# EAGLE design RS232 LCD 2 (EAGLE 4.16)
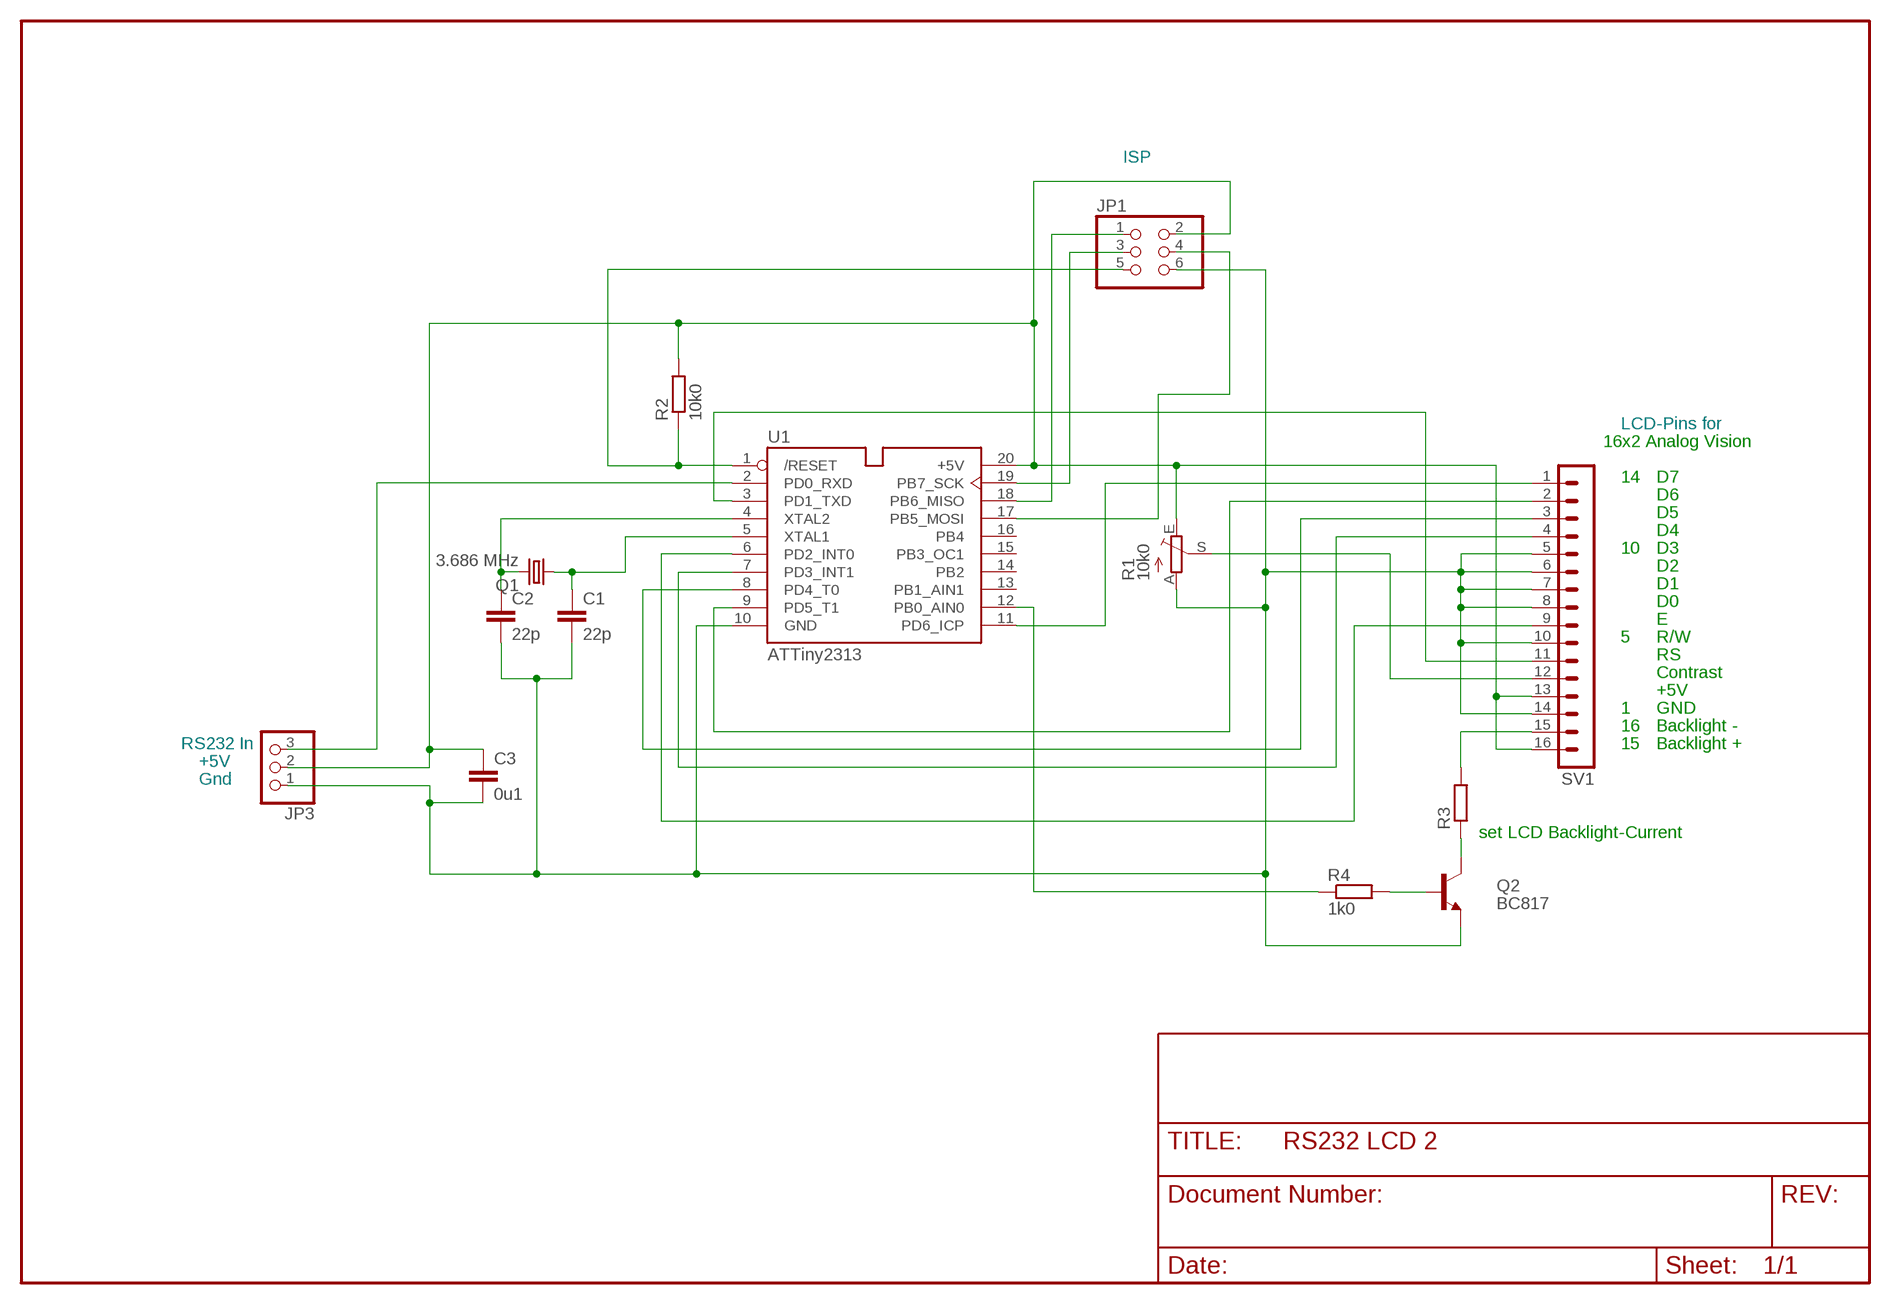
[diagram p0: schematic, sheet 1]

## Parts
C1  22p  C-EU050-025X075  [C050-025X075]
C2  22p  C-EU050-025X075  [C050-025X075]
C3  0u1  C-EU025-030X050  [C025-030X050]
JP1  PINHD-2X3  [2X03]
JP3  PINHD-1X3  [1X03]
Q1  3.686 MHz  CRYSTALHC18U-V  [HC18U-V]
Q2  BC817  BC817-16LT1SMD  [SOT23-BEC]
R1  10k0  TRIM_EU-PT10  [PT-10]
R2  10k0  R-EU_0207/10  [0207/10]
R3  R-EU_0207/10  [0207/10]
R4  1k0  R-EU_0207/10  [0207/10]
SV1  MA16-1  [MA16-1]
U1  ATTiny2313  AT90S2313_SO-20  [SO-20]

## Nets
+5V [Power]: C3.1 JP1.2 JP3.2 R1.E R2.2 SV1.13 SV1.16 U1.20(+5V)
BL- [Power]: R3.2 SV1.15
BL_BASE: Q2.B R4.2
BL_COLLECTOR: Q2.C R3.1
BL_CONTROL: R4.1 U1.12(PB0_AIN0)
CONTR: R1.S SV1.12
D4: SV1.4 U1.7(PD3_INT1)
D5: SV1.3 U1.8(PD4_T0)
D6: SV1.2 U1.9(PD5_T1)
D7: SV1.1 U1.11(PD6_ICP)
E: SV1.9 U1.6(PD2_INT0)
GND [Power]: C1.2 C2.2 C3.2 JP1.6 JP3.1 Q2.E R1.A SV1.5 SV1.6 SV1.7 SV1.8 SV1.10 SV1.14 U1.10(GND)
MISO: JP1.1 U1.18(PB6_MISO)
MOSI: JP1.4 U1.17(PB5_MOSI)
R/S: SV1.11 U1.3(PD1_TXD)
RST: JP1.5 R2.1 U1.1(/RESET)
RXD: JP3.3 U1.2(PD0_RXD)
SCK: JP1.3 U1.19(PB7_SCK)
XTAL1: C1.1 Q1.1 U1.5(XTAL1)
XTAL2: C2.1 Q1.2 U1.4(XTAL2)
Unconnected: U1.13(PB1_AIN1) U1.14(PB2) U1.15(PB3_OC1) U1.16(PB4)

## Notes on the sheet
- ISP
- LCD-Pins for
- 16x2 Analog Vision
- 14 | D7
- D6
- D5
- D4
- 10 | D3
- D2
- D1
- D0
- E
- 5 | R/W
- RS
- Contrast
- +5V
- 1 | GND
- 16 | Backlight -
- RS232 In | 15 | Backlight +
- +5V
- Gnd
- set LCD Backlight-Current

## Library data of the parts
C1-C3 = rcl:C-EU: CAPACITOR, European symbol
JP1 = pinhead:PINHD-2X3: PIN HEADER
JP3 = pinhead:PINHD-1X3: PIN HEADER
Q1 = crystal:CRYSTAL: CRYSTAL
Q2 = transistor-npn:BC817*: NPN Transistor
R1 = pot:TRIM_EU-: POTENTIOMETER
R2-R4 = rcl:R-EU_: RESISTOR, European symbol
SV1 = con-lstb:MA16-1
U1 = atmel_prototype_header:AT90S2313: 8-bit AVR Microcontroller with 2K bytes In-System Programmable Flash

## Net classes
0 default: width 0.254 mm
1 Power: width 0.635 mm

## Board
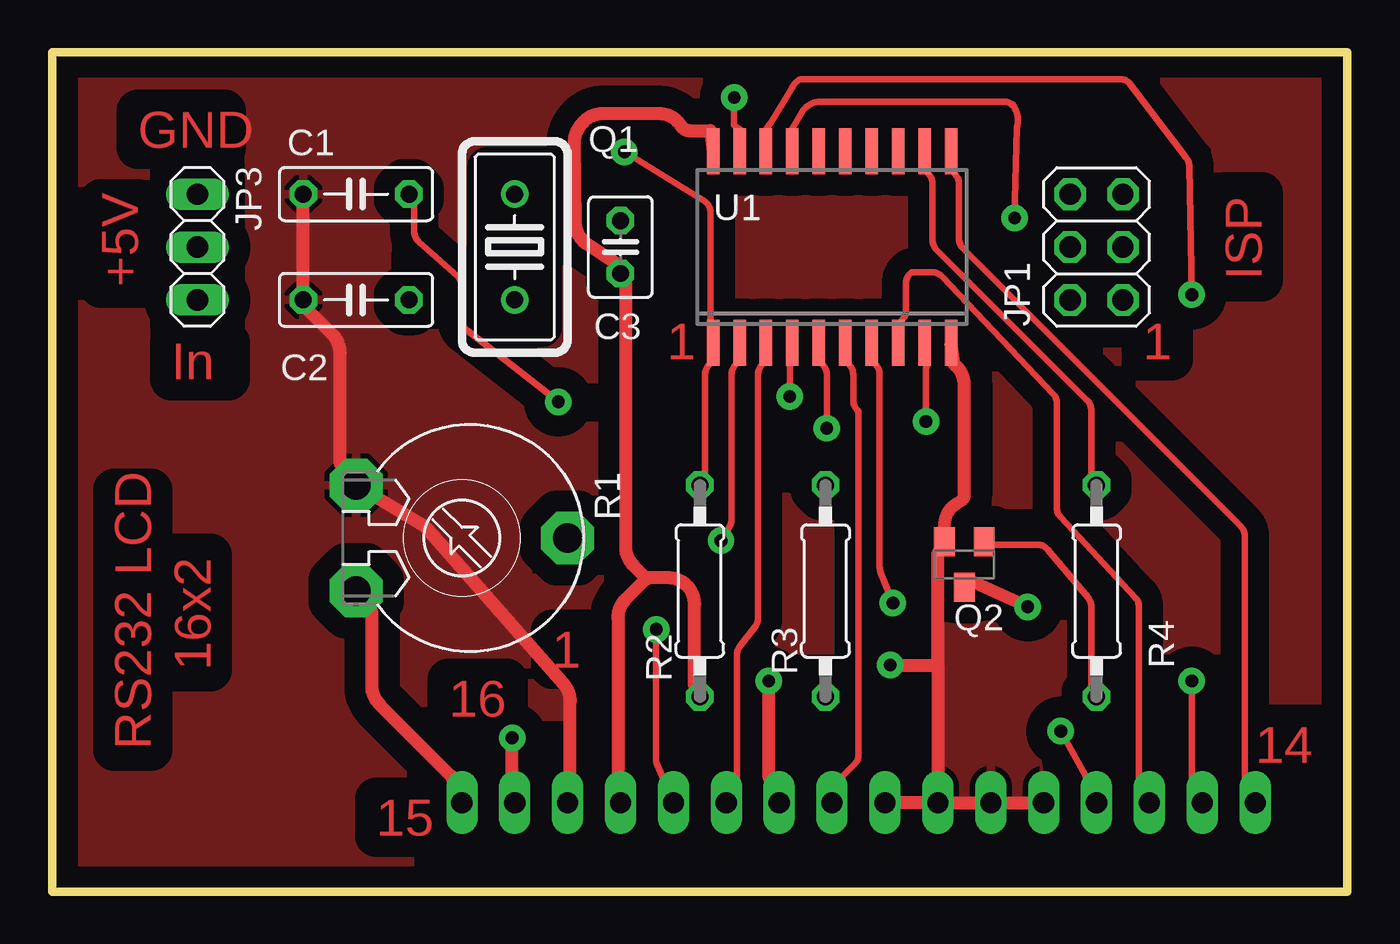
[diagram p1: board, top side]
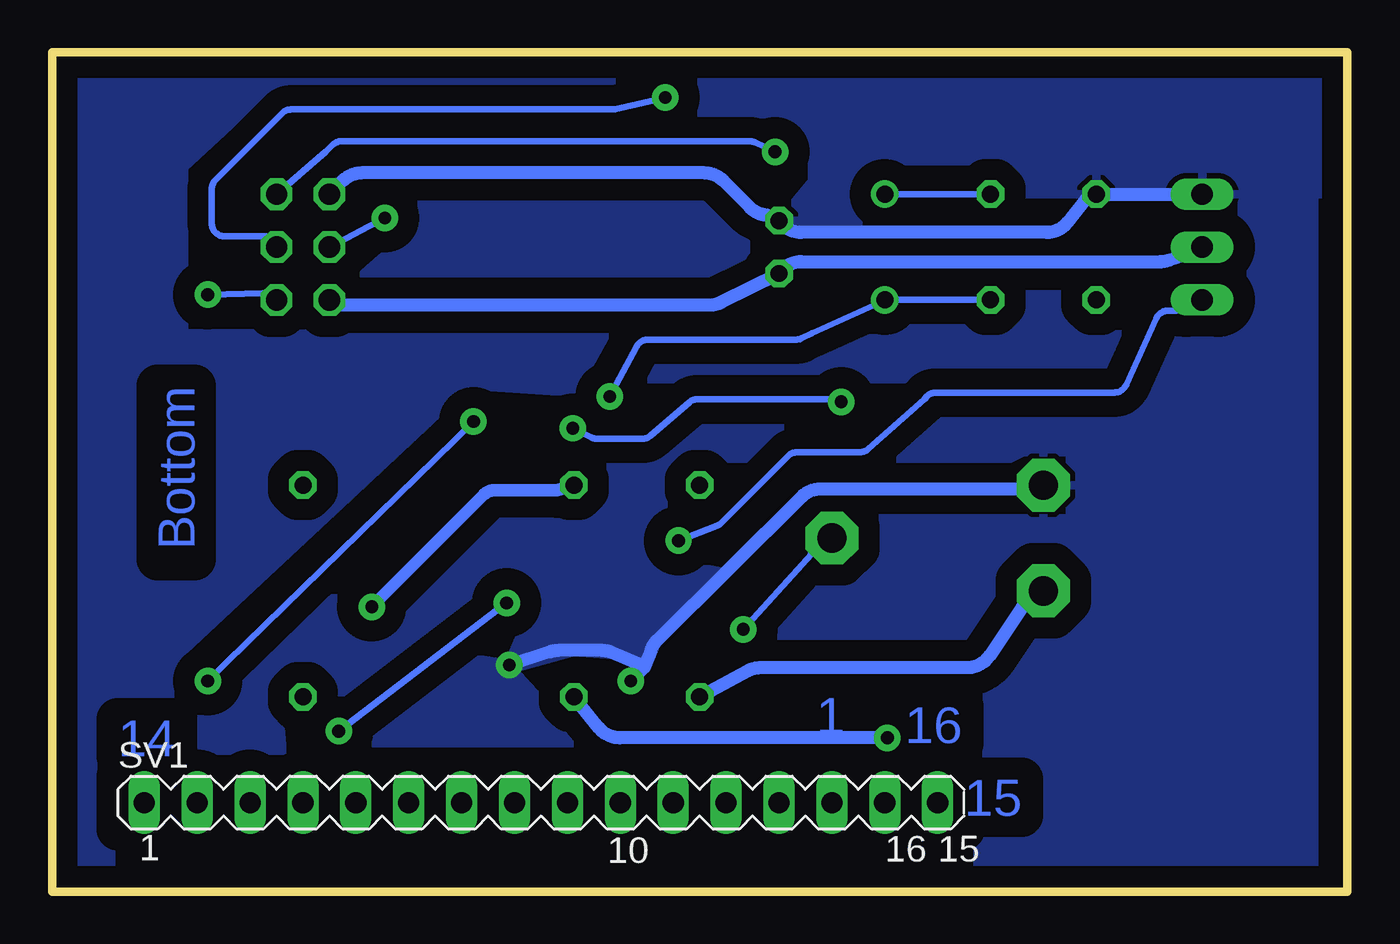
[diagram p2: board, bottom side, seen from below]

Size 62.21 x 40.31 mm. Coordinates in mm from the lower left corner, seen from the top.
Outline: 0,0 62.21,0 62.21,40.31 0,40.31 0,0
Copper layers (1*16): Top 0.035mm / dielectric 1.5mm / Bottom 0.035mm
Design rules "Doppelt_eigene_grosse_vias": minimum track width 12mil, minimum drill 24mil, track to track 15mil, track to pad 15mil, pad to pad 20mil, via to via 20mil, smd to smd 8mil, copper to edge 20mil, drill to drill 8mil, minimum pad ring 10mil, minimum via ring 13mil, stop-mask expansion 4mil, vias tented up to drill 0mil, thermal gap 10mil
tRestrict: area 5.7,27.1 to 8.2,34.8; area 47.6,27.1 to 52.7,34.8; area 21,27.1 to 23.5,34.8; area 18.4,-0.8 to 59.1,1.7
bRestrict: area 18.4,3 to 59.1,5.5
vRestrict: area 31.1,28.4 to 43.8,33.5

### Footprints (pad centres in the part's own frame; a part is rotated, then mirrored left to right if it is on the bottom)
C050-025X075 = drill 0.813 octagon: 1 -2.54,0; 2 2.54,0
C025-030X050 = drill 0.813 octagon: 1 -1.27,0; 2 1.27,0
2X03 = drill 1.016 octagon: 1 -2.54,-1.27; 2 -2.54,1.27; 3 0,-1.27; 4 0,1.27; 5 2.54,-1.27; 6 2.54,1.27
1X03 = drill 1.016 long: 1 -2.54,0; 2 0,0; 3 2.54,0
HC18U-V = drill 0.813 round: 1 -2.54,0; 2 2.54,0
SOT23-BEC = smd 1 x 1.4: B -0.95,-1.1; C 0,1.1; E 0.95,-1.1
PT-10 = drill 1.4 pad 2.54 octagon: A -2.54,-5.08; E 2.54,-5.08; S 0,5.08
0207/10 = drill 0.813 octagon: 1 -5.08,0; 2 5.08,0
MA16-1 = drill 1.016 long: 1 -19.05,0; 2 -16.51,0; 3 -13.97,0; 4 -11.43,0; 5 -8.89,0; 6 -6.35,0; 7 -3.81,0; 8 -1.27,0; 9 1.27,0; 10 3.81,0; 11 6.35,0; 12 8.89,0; 13 11.43,0; 14 13.97,0; 15 16.51,0; 16 19.05,0
SO-20 = smd 0.6 x 2.2: 1 -5.715,-4.6; 2 -4.445,-4.6; 3 -3.175,-4.6; 4 -1.905,-4.6; 5 -0.635,-4.6; 6 0.635,-4.6; 7 1.905,-4.6; 8 3.175,-4.6; 9 4.445,-4.6; 10 5.715,-4.6; 11 5.715,4.6; 12 4.445,4.6; 13 3.175,4.6; 14 1.905,4.6; 15 0.635,4.6; 16 -0.635,4.6; 17 -1.905,4.6; 18 -3.175,4.6; 19 -4.445,4.6; 20 -5.715,4.6

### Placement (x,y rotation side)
C1  14.6,33.49 180 top
C2  14.6,28.41 180 top
C3  27.3,30.95 90 top
JP1  50.16,30.95 90 top
JP3  6.98,30.95 270 top
Q1  22.22,30.95 270 top
Q2  43.81,15.71 180 top
R1  19.68,16.98 270 top
R2  31.11,14.44 270 top
R3  37.14,14.44 270 top
R4  50.16,14.44 270 top
SV1  38.73,4.28 0 bottom
U1  37.46,30.95 0 top

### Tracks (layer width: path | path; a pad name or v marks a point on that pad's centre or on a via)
+5V
  Top 0.635: SV1.16 19.17,5.55 15.73,8.99 arc-45 15.36,9.89 15.36,13.42 R1.E | 28.57,15.07 27.55,14.05 arc45 27.17,13.15 27.17,5.55 SV1.13 | 28.57,15.07 29.59,15.07 arc-90 30.86,13.81 30.86,9.87 R2.2 | U1.20 31.62,36.54 30.61,36.54 arc-58 30.21,36.76 arc58 29.13,37.36 26.44,37.36 arc55 25.4,36.81 25.31,36.68 arc35 25.08,35.95 25.13,32.13 arc56 25.7,31.09 27.05,30.19 C3.1 27.55,29.17 27.55,16.55 arc45 27.93,15.66 28.57,15.01 28.57,15.07
  Bottom 0.635: R2.2 30.6,9.61 28.79,10.6 arc29 28.18,10.76 18.26,10.76 arc-56 17.21,11.32 15.62,13.68 R1.E | JP3.2 8.25,30.44 8.54,30.33 arc21 8.99,30.25 26.22,30.25 arc-48 27.17,29.82 C3.1 30.08,28.29 arc27 30.65,28.16 48.51,28.16 JP1.2
BL-  (via drill 0.61)
  Top 0.635: v22.09,7.39 22.09,5.55 SV1.15
  Bottom 0.635: v22.09,7.39 34.95,7.39 arc51 35.94,7.86 36.95,9.11 R3.2
BL_BASE
  Top 0.305: 45.08,16.47 Q2.B 44.76,16.66 47.32,16.66 arc-50 47.81,16.43 49.76,14.11 arc-40 49.91,13.7 49.91,9.87 R4.2
BL_COLLECTOR  (via drill 0.61)
  Top 0.305: 44.06,14.95 Q2.C
  Top 0.61: v46.86,13.68 44.06,14.95
  Bottom 0.61: v46.86,13.68 41.46,19.08 arc45 41.01,19.27 37.97,19.27 R3.1
BL_CONTROL
  Top 0.305: U1.12 42.03,34.51 42.1,34.44 arc-45 42.29,33.99 42.29,31.28 arc45 42.47,30.83 49.72,23.58 arc-45 49.91,23.13 49.91,20.03 R4.1
CONTR  (via drill 0.61)
  Top 0.305: SV1.12 29.07,6.06 arc-23 29.02,6.32 v29.02,12.6
  Bottom 0.305: v29.02,12.6 25.71,16.22 25.78,16.22 R1.S
D4  (via drill 0.61)
  Top 0.305: v40.38,13.87 39.79,15.34 arc-22 39.75,15.58 39.75,24.85 arc45 39.56,25.29 39.49,25.36 U1.7 | v48.45,7.71 49.65,5.55 SV1.4
  Bottom 0.305: v40.38,13.87 v48.45,7.71
D5
  Top 0.305: U1.8 40.76,27.39 40.83,27.46 arc45 41.02,27.91 41.02,29.23 arc-45 41.2,29.68 arc-45 41.37,29.74 42.27,29.74 arc-47 42.73,29.54 48.08,23.89 arc-43 48.26,23.46 48.26,18.43 arc43 48.42,18 52.02,14.11 arc-43 52.19,13.68 52.19,5.55 SV1.3
D6  (via drill 0.61)
  Top 0.305: v41.97,22.57 41.97,25.11 42.03,25.36 U1.9 | v54.73,10.12 54.73,5.55 SV1.2
  Bottom 0.305: v54.73,10.12 v41.97,22.57
D7
  Top 0.305: U1.11 43.3,34.51 43.37,34.44 arc-45 43.56,33.99 43.56,31.34 arc45 43.74,30.89 57.09,17.55 arc-45 57.27,17.1 57.27,5.55 SV1.1
E
  Top 0.305: U1.6 38.22,25.36 38.29,25.29 arc-45 38.48,24.85 38.48,23.59 arc45 38.66,23.14 arc-45 38.73,22.98 38.73,6.57 arc-45 38.54,6.13 37.97,5.55 SV1.9
GND  (via drill 0.61)
  Top 0.61: Q2.E 42.86,17.56 arc-57 43.42,18.63 43.69,18.8 arc56 43.81,19.03
  Top 0.635: C1.2 C2.2 12.31,27.9 13.47,26.75 arc-45 13.84,25.85 13.84,20.54 R1.A 17.73,17.65 arc-18 18.03,17.4 24.57,9.97 arc-41 24.89,9.14 24.89,5.55 SV1.14 | SV1.5 SV1.6 SV1.7 | 42.54,10.88 42.54,16.22 Q2.E | 42.54,10.88 SV1.7 | 43.81,19.03 43.81,24.33 arc45 43.44,25.23 43.3,25.36 U1.10 | SV1.7 SV1.8 | v34.41,10.12 34.41,5.55 SV1.10 | v40.25,10.88 42.54,10.88
  Bottom 0.635: JP3.1 C1.2 12.57,33.24 13.46,32.12 arc51 14.45,31.65 26.22,31.65 arc48 27.17,32.08 C3.2 27.81,32.47 arc45 28.68,32.83 29.98,34.13 arc-45 30.87,34.51 47.35,34.51 arc-45 48.25,34.13 JP1.6 | 33.78,10.76 v34.41,10.12 | 33.78,10.76 33.43,11.65 arc24 33.14,12.09 26.21,18.96 arc45 25.32,19.33 15.3,19.33 R1.A | v40.25,10.88 38.29,11.52 arc18 37.89,11.58 35.81,11.58 arc23 35.32,11.48 33.9,10.88 33.78,10.76
  pour Bottom (isolate 1.016): 6.98,33.49 15.55,33.49 15.87,33.81 15.87,34.12 16.82,35.08 22.22,35.08 23.49,33.81 23.49,33.49 24.13,32.86 25.4,32.86 25.71,33.17 25.71,35.71 26.66,36.67 30.79,36.67 31.43,37.3 31.43,40.16 0,40.16 0,33.49
  pour Bottom (isolate 1.016): 1.58,34.12 1.58,0.15 17.77,0.15 17.77,3.01 18.09,3.33 15.23,3.33 14.92,3.64 14.92,5.23 15.55,5.87 17.77,5.87 18.41,6.5 18.41,9.68 18.09,9.68 15.23,12.54 13.65,12.54 13.33,12.85 13.33,16.03 15.87,16.03 15.87,13.81 18.09,11.58 28.25,11.58 28.25,12.54 25.4,15.39 23.49,15.39 23.49,17.61 22.86,17.93 13.33,17.93 13.33,21.11 15.55,21.11 16.19,20.79 22.22,20.79 19.68,23.01 10.79,23.01 8.57,27.14 5.08,27.14 5.08,33.17
  pour Top (isolate 1.016): 11.74,33.81 11.74,35.08 23.81,35.08 24.44,37.3 26.03,38.25 31.11,38.25 31.11,40.16 0,40.16 0,-0.16 17.46,-0.16 17.46,5.55 14.28,9.36 14.28,12.54 12.38,13.81 13.01,16.03 15.55,16.35 16.51,14.44 16.51,9.68 20,6.5 20.95,8.41 24.76,8.41 24.76,9.68 18.09,17.61 14.6,19.52 13.97,26.19 12.38,28.09 12.06,33.17
  pour Top (isolate 1.016): 12.06,33.49 11.74,35.08 16.19,35.08 15.87,18.89 14.28,21.11 13.97,26.5 12.38,27.78 12.06,28.41
  pour Top (isolate 1.016): 14.6,19.52 22.54,12.54 26.35,12.54 26.35,15.07 22.86,15.07 22.86,18.25 23.49,18.89 26.35,18.89 26.35,22.38 23.49,22.38 19.05,26.82 14.6,26.82 14.6,19.84
  pour Top (isolate 1.016): 12.06,33.49 12.06,40.16 24.76,40.16 23.81,35.71 24.13,34.44 24.13,30.95 25.71,29.36 26.35,28.09 26.35,23.96 25.4,23.96 24.76,24.6 24.13,24.6 20.32,27.78 20.32,29.36 18.09,31.59 18.09,35.71 14.28,35.71 14.28,33.17 11.74,33.49
  pour Bottom (isolate 1.016): 40.32,10.95 36.82,7.14 46.99,7.14 42.22,11.27
  pour Bottom (isolate 1.016): 40.32,10.95 38.41,11.58 33.97,11.27 30.16,15.39 33.33,16.03 33.33,17.61 32.38,18.25 32.38,19.84 32.06,20.79 27.93,20.79 25.71,22.7 31.11,22.7 33.33,20.79 35.87,20.79 35.87,18.57 40.95,18.25 49.21,10 47.94,9.04 40.95,14.76 39.68,15.07 39.05,14.12 39.37,13.17
  pour Top (isolate 1.016): 42.86,4.6 42.86,12.85 49.21,12.85 48.89,10 47.3,8.73 47.3,6.5 47.62,4.28 42.54,4.28
  pour Bottom (isolate 1.016): 40.32,10.95 38.41,14.44 40.63,15.39 48.57,9.36 50.8,10.63 51.43,10 51.11,6.5 55.24,6.5 55.24,8.73 53.65,9.36 53.34,10.63 41.91,21.43 40.95,21.43 40.63,23.01 38.41,23.01 38.1,20.16 41.59,19.84 48.26,13.17 46.35,12.22 40.95,17.3 36.82,17.3 36.82,11.58 40.32,10.63
  pour Bottom (isolate 1.016): 12.06,33.49 12.06,35.08 23.49,35.08 23.49,31.59 26.66,31.59 27.3,32.22 25.71,34.12 25.71,36.67 12.06,36.67
MISO  (via drill 0.61)
  Top 0.305: U1.18 34.29,36.4 arc-45 34.47,36.85 35.5,38.51 arc-45 35.95,39.01 51.28,39.01 arc-48 51.75,38.81 54.44,35.25 arc-41 54.61,34.84 v54.73,28.66
  Bottom 0.305: v54.73,28.66 52.07,28.73 JP1.1
MOSI  (via drill 0.61)
  Top 0.305: v46.22,32.35 46.34,36.67 arc52 46.11,37.82 46.08,37.79 arc40 45.68,37.94 36.77,37.94 arc45 36,37.43 35.55,36.67 U1.17
  Bottom 0.305: v46.22,32.35 JP1.4
N$1
  pour Bottom (isolate 1.016): 62.23,40.16 62.23,-0.16 59.37,-0.16 59.37,8.73 56.19,8.73 56.19,11.27 42.22,24.28 37.14,23.96 35.55,26.82 55.88,26.82 55.88,34.76 52.07,38.25 34.29,38.57 33.33,40.16
N$2
  pour Top (isolate 1.016): 62.23,40.16 62.23,8.73 58.1,8.73 58.1,17.3 49.21,27.14 55.88,27.14 55.88,35.71 51.75,40.16
N$3
  pour Top (isolate 1.016): 32.7,33.49 41.27,33.49 41.27,30.95 40.32,30.32 40.32,28.09 32.7,28.09 32.7,33.17
N$4
  pour Top (isolate 1.016): 53.02,11.58 56.51,11.58 56.51,16.98 51.11,22.06 51.11,20.47 51.11,18.57 49.52,18.25 52.7,14.12 52.7,11.58
N$5
  pour Top (isolate 1.016): 33.97,11.58 37.78,11.58 37.78,17.61 34.92,19.2 34.92,12.85 34.29,11.58
N$6
  pour Top (isolate 1.016): 44.76,25.87 44.76,18.57 47.3,18.57 47.3,23.65 45.08,25.87
N$8
  pour Bottom (isolate 1.016): 28.89,31.27 30.79,33.81 45.08,33.81 45.08,31.59 47.62,29.36 30.79,29.36 28.89,30.32 28.89,30.95
N$9
  pour Bottom (isolate 1.016): 11.43,24.6 33.65,24.6 33.33,25.87 25.4,25.87 22.54,27.14 16.19,27.14 15.55,27.46 15.55,29.36 13.33,29.36 13.33,27.46 10.16,27.14
N$10
  pour Top (isolate 1.016): 23.81,24.6 26.98,24.6 26.98,28.73 24.76,30.63 24.13,32.54 20.32,32.22 20.32,27.46 23.81,24.28
R/S
  Top 0.305: U1.3 34.16,25.36 34.09,25.29 arc45 33.9,24.85 33.9,13.13 arc-37 33.77,12.75 33.02,11.75 arc37 32.89,11.37 32.89,5.55 SV1.11
RST  (via drill 0.61)
  Top 0.305: R2.1 31.36,20.03 31.36,24.85 arc-45 31.55,25.29 31.62,25.36 U1.1 31.62,27.39 31.62,32.63 arc58 31.32,33.17 v27.49,35.52
  Bottom 0.305: v27.49,35.52 28.44,35.97 arc-25 28.71,36.03 48.31,36.03 arc-45 48.76,35.84 49.08,35.52 JP1.5
RXD  (via drill 0.61)
  Top 0.305: v32.13,16.85 32.54,17.53 arc32 32.63,17.86 32.63,24.85 arc-45 32.82,25.29 32.89,25.36 U1.2
  Bottom 0.305: JP3.3 8.25,27.9 8.6,27.9 arc-66 9.18,27.53 10.62,24.34 arc66 11.2,23.96 19.76,23.96 arc-40 20.18,23.81 20.32,23.65 22.99,21.27 arc42 23.41,21.11 26.4,21.11 arc-45 26.85,20.92 30.06,17.71 arc24 30.28,17.57 v32.13,16.85
SCK  (via drill 0.61)
  Top 0.305: v32.76,38.12 32.76,36.79 33.14,36.54 U1.19
  Bottom 0.305: v32.76,38.12 35.17,37.57 arc13 35.31,37.55 50.72,37.55 arc-45 51.17,37.37 54.35,34.18 arc-45 54.54,33.73 54.54,32.09 arc-90 53.91,31.46 51.94,31.46 JP1.3
XTAL1  (via drill 0.61)
  Top 0.305: v37.21,22.25 37.21,24.85 arc45 37.02,25.29 36.95,25.36 U1.5 | v24.32,23.52 19.92,26.95 arc-52 19.68,27.45 19.68,29.08 arc48 19.47,29.55 17.61,31.21 arc-48 17.39,31.68 17.39,32.98 C1.1
  Bottom 0.305: C1.1 Q1.1 | v37.21,22.25 36.32,21.81 arc-27 36.04,21.74 33.88,21.74 arc-41 33.47,21.89 31.61,23.5 arc41 31.19,23.65 24.44,23.65 v24.32,23.52
XTAL2  (via drill 0.61)
  Top 0.305: v35.43,23.77 35.43,25.36 U1.4
  Bottom 0.305: C2.1 Q1.2 22.73,28.16 25.71,26.82 26.21,26.57 arc27 26.5,26.5 33.59,26.5 arc-62 34.15,26.17 v35.43,23.77

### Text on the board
Top: GND | +5V | ISP | 1 | 1 | In | 1 | 16x2 | 16 | RS232 LCD | 14 | 15
Bottom: Bottom | 1 | 16 | 14 | 15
